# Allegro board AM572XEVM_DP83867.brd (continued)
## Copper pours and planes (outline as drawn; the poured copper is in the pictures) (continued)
GND on TOP: 96.37,66.14 96.37,72.24 99.92,72.24 99.92,66.14
GND on TOP: 28.07,76.96 28.07,81.66 27.81,81.92 23.5,81.92 22.35,83.06 22.35,93.22 22.86,93.73 27.39,93.73 27.79,93.32 27.79,87.18 28.11,86.87 29.72,86.87 30.1,86.49 30.1,83.44 30.61,82.93 30.61,80.52 30.86,80.26 35.69,80.26 35.81,80.14 35.81,78.99 35.69,78.87 34.04,78.87 33.4,79.5 30.86,79.5 30.61,79.25 30.61,76.96 30.86,76.71 32.13,76.71 32.26,76.58 32.26,75.95 32.13,75.82 26.54,75.82 26.42,75.95 26.42,76.58 26.54,76.71 27.81,76.71
GND on TOP: 82.58,65.66 82.58,71.75 86.13,71.75 86.13,65.66
GND on TOP: 109.47,24.13 109.47,36.96 111.38,36.96 111.38,24.13
GND on TOP: 101.6,40.89 101.6,45.59 101.35,45.85 99.44,45.85 98.74,46.55 98.74,52.22 99.45,52.93 100.65,52.93 103.31,50.27 103.31,47.69 104.14,46.86 104.14,44.45 104.39,44.2 108.08,44.2 108.2,44.07 108.2,43.56 108.08,43.43 104.39,43.43 104.14,43.18 104.14,40.89 104.39,40.64 105.66,40.64 105.79,40.51 105.79,39.88 105.66,39.75 100.08,39.75 99.95,39.88 99.95,40.51 100.08,40.64 101.35,40.64
GND on BOTTOM: 55.44,28.77 79.18,28.77 79.18,52.51 55.44,52.51 ; 6 cut-outs
GND on BOTTOM: 28.58,73.15 32.39,73.15 32.64,72.9 32.64,71.37 32.39,71.12 28.58,71.12 28.32,71.37 28.32,72.9
GND on BOTTOM: 46.04,25.39 46.04,24.43 46.29,24.18 47.05,24.18 47.5,24.63 47.5,24.75 47.31,24.94 47.24,24.94 46.74,24.5 46.48,24.5 46.36,24.63 46.36,25.32 46.29,25.39
GND on BOTTOM: 89.59,73.05 88.06,71.53 85.5,71.53 83.39,69.42 83.39,62.48 87.3,58.57 93.01,58.57 96.24,61.8 96.24,63.09 96.39,63.25 97.74,63.25 98.2,63.7 98.2,65.81 97,67.01 97,71.07 95.02,73.05
GND on BOTTOM: 103.5,44.58 103.76,44.32 103.76,41.78 104.01,41.53 105.66,41.53 105.79,41.4 105.79,39.88 105.66,39.75 100.2,39.75 100.08,39.88 100.08,40.64 100.2,40.77 100.58,40.77 100.71,40.89 100.71,42.16 100.58,42.29 100.2,42.29 100.08,42.42 100.08,42.67 100.2,42.8 101.73,42.8 101.98,43.05 101.98,44.32 102.23,44.58
GND on BOTTOM: 60.81,82.09 60.81,82.96 61.06,83.21 63.37,83.21 63.73,82.85 63.73,81.46 63.45,81.18 62.94,81.18 62.23,81.89 61.01,81.89
GND on BOTTOM: 103.76,50.55 103.76,49.15 103.5,48.9 99.7,48.9 99.44,49.15 99.44,50.55 99.7,50.8 103.5,50.8
GND on BOTTOM: 97.51,70.89 97.51,67.74 98.73,66.52 98.73,63.45 99.29,62.89 100.13,62.89 100.94,62.08 100.94,59.54 101.65,58.83 109.25,58.83 109.87,59.45 109.87,62.62 111.68,64.44 111.68,69.19 107.62,73.25 102.06,73.25 102.03,73.28 99.9,73.28
GND on BOTTOM: 25.91,87.12 31.9,87.12 32.44,86.58 32.44,85.15 32.39,85.09 25.91,85.09 25.78,85.22 25.78,87
GND on BOTTOM: 46.04,47.79 46.04,46.84 46.29,46.58 47.05,46.58 47.5,47.03 47.5,47.16 47.31,47.35 47.24,47.35 46.74,46.9 46.48,46.9 46.36,47.03 46.36,47.73 46.29,47.79
GND on BOTTOM: 67.06,62.74 66.8,62.48 65.02,62.48 64.77,62.74 64.77,63.75 65.02,64.01 66.8,64.01 67.06,63.75
GND on BOTTOM: 46.04,58.99 46.04,58.04 46.29,57.78 47.05,57.78 47.5,58.23 47.5,58.36 47.31,58.55 47.24,58.55 46.74,58.1 46.48,58.1 46.36,58.23 46.36,58.93 46.29,58.99
GND on BOTTOM: 71.12,63.5 71.37,63.75 73.15,63.75 73.41,63.5 73.41,61.98 73.15,61.72 72.9,61.72 72.39,62.23 71.37,62.23 71.12,62.48
GND on BOTTOM: 56.77,65.48 56.77,66.65 56.34,67.08 56.34,67.49 56.44,67.59 57.76,67.59 58.39,66.95 58.39,65.81 57.91,65.33 56.92,65.33
GND on BOTTOM: 32.39,66.8 32.64,66.55 32.64,64.64 32.89,64.39 34.54,64.39 34.67,64.26 34.67,64.01 34.54,63.88 32.77,63.88 28.96,63.88 28.83,64.01 28.83,65.28 28.96,65.41 30.61,65.41 30.86,65.66 30.86,66.55 31.12,66.8
GND on BOTTOM: 66.9,83.77 66.37,83.77 65.81,83.21 64.21,83.21 64.06,83.06 64.06,81.94 64.13,81.86 65.91,81.86 66.19,81.58 66.19,81.31 66.42,81.08 66.93,81.08 67.06,81.2 67.06,81.64 67.26,81.84 69.09,81.84 69.27,82.02 69.27,82.91 68.96,83.21 67.46,83.21
GND on BOTTOM: 83.57,79.5 83.57,89.15 83.82,89.41 86.36,89.41 86.61,89.15 86.61,79.5 86.36,79.25 83.82,79.25
GND on BOTTOM: 72.29,83.21 69.7,83.21 69.49,83.01 69.49,81.18 69.72,80.95 70.13,80.95 70.38,81.2 70.38,81.58 70.61,81.81 72.29,81.81 72.59,82.12 72.59,82.91
GND on BOTTOM: 27.18,46.61 27.43,46.86 30.73,46.86 30.73,48.26 30.86,48.39 31.24,48.39 31.5,48.13 31.5,42.8 31.24,42.55 27.43,42.55 27.18,42.8
GND on BOTTOM: 62.23,62.74 61.98,62.48 60.2,62.48 59.94,62.74 59.94,63.75 60.2,64.01 61.98,64.01 62.23,63.75
GND on BOTTOM: 57.4,62.74 57.15,62.48 55.37,62.48 55.12,62.74 55.12,63.75 55.37,64.01 57.15,64.01 57.4,63.75
GND on BOTTOM: 29.97,80.77 30.23,80.52 30.23,77.98 29.97,77.72 29.46,77.72 29.34,77.6 29.34,77.09 29.46,76.96 32.13,76.96 32.26,76.83 32.26,76.07 32.13,75.95 26.54,75.95 26.42,76.07 26.42,78.87 26.54,78.99 28.19,78.99 28.45,79.25 28.45,80.52 28.7,80.77
GND on GND_L2, GND_L4, GND_L11: outline of 82 points within 14.1,1.52 123.06,106.05
GND on PWR_L6: 86.49,7.87 86.74,7.62 107.82,7.62 112.78,12.57 112.78,39.62 112.52,39.88 111.38,39.88 111,40.26 111,42.16 110.74,42.42 104.65,42.42 104.39,42.16 104.39,34.16 104.01,33.78 99.31,33.78 99.06,33.53 99.06,24.13 98.68,23.75 86.74,23.75 86.49,23.5
GND on GND_L9: outline of 82 points within 14.1,1.52 123.06,106.05 ; 14 cut-outs
GND_EARTH on BOTTOM (solid shape): 88.03,0.2 84.69,0.2 84.69,2.7 88.03,2.7
GND_EARTH on BOTTOM (solid shape): 84.5,4.03 84.28,4.03 84.28,1 84.16,0.72 83.88,0.6 83.38,0.6 83.09,0.72 82.97,1 82.97,3.05 82.5,3.05 82.5,5.43 84.5,5.43
GND_EARTH on BOTTOM (solid shape): 90.22,3.05 89.72,3.05 89.72,1 89.61,0.72 89.33,0.6 88.82,0.6 88.54,0.72 88.42,1 88.42,4.03 88.22,4.03 88.22,5.43 90.22,5.43
GND_EARTH on TOP, BOTTOM, GND_L2, INT_L3, GND_L4, SIG_L5, PWR_L6, PWR_L7, SIG_L8, GND_L9, SIG_L10, GND_L11: outline of 95 points within 13.08,0.38 124.08,107.19
GND_SIGNAL on SIG_L8: 24.89,1.52 24.64,1.78 24.64,14.73 24.89,14.99 45.97,14.99 51.69,20.7 51.69,23.62 51.94,23.88 62.48,23.88 62.87,23.5 62.87,12.45 62.61,12.19 52.32,12.19 51.44,11.3 51.44,1.78 51.18,1.52
VDD_1.1 on PWR_L6: 86.49,36.96 86.74,37.21 97.28,37.21 97.66,37.59 97.66,42.16 97.92,42.42 103.89,42.42 104.14,42.16 104.14,34.29 103.89,34.04 99.19,34.04 98.81,33.66 98.81,24.26 98.55,24 86.74,24 86.49,24.26
VDD_1V0 on TOP: 55.63,66.9 55.19,67.34 54.08,67.34 53.8,67.06 53.8,65.46 54.33,64.92 55.45,64.92 55.63,65.1
VDD_1V0 on TOP: 86.69,74.27 86.69,75.59 87.02,75.92 87.6,75.92 87.91,75.62 87.91,74.63 87.5,74.22 86.74,74.22
VDD_1V0 on TOP: 111.25,74.93 111.25,75.31 110.97,75.59 110.97,76.15 111.4,76.58 111.89,76.58 112.34,76.12 112.34,75.59 112.06,75.31 112.06,74.88 111.3,74.88
VDD_1V0 on BOTTOM: 56.11,66.55 55.65,67.01 54.33,67.01 54.13,66.8 54.13,65.23 54.41,64.95 55.75,64.95 56.11,65.3
VDD_1V0 on SIG_L8: 54.76,67.26 53.77,67.26 51.26,69.77 45.75,69.77 44.96,70.56 42.32,70.56 41.38,71.5 41.38,76.78 44.88,80.29 44.88,85.93 45.87,86.92 75.62,86.92 75.95,86.59 79.4,86.59 85.67,80.31 85.67,75.74 86.44,74.98 112.65,74.98 112.93,75.26 112.93,76.86 112.52,77.27 89.61,77.27 88.9,77.98 88.9,81.76 80.44,90.22 49.68,90.22 48.69,91.21 44.32,91.21 37.36,84.25 37.36,71.12 40.84,67.64 44.98,67.64 45.57,67.06 51.1,67.06 52.2,65.96 53.44,65.96 54.05,65.35 54.81,65.35 55.07,65.61 55.07,66.95
VDD_1V8 on TOP: 56.64,59.44 56.64,60.45 56.9,60.71 58.67,60.71 58.93,60.45 58.93,59.44 58.67,59.18 56.9,59.18
VDD_1V8 on BOTTOM: 58.93,59.44 58.67,59.18 56.9,59.18 56.64,59.44 56.64,60.45 56.9,60.71 58.67,60.71 58.93,60.45
VDD_1V8 on PWR_L7: 57.28,54.74 57.28,66.29 54.74,68.83 54.74,70.1 54.99,70.36 66.29,70.36 66.55,70.1 66.55,48.64 65.91,48.01 65.91,44.7 65.66,44.45 63.37,44.45 63.12,44.7 63.12,58.04 64.01,58.93 64.01,60.83 63.63,61.21 59.94,61.21 59.56,60.83 59.56,54.74 59.31,54.48 57.53,54.48
VDD_1V8 on PWR_L7: 72.64,42.16 72.77,42.04 74.8,42.04 74.93,42.16 74.93,46.61 74.8,46.74 73.53,46.74 73.41,46.61 73.41,44.2 73.15,43.94 72.9,43.94 72.64,43.69
VDD_1V8 on SIG_L8: 63.25,69.09 63.25,68.33 62.99,68.07 62.61,68.07 61.59,69.09 61.59,72.14 61.85,72.39 69.98,72.39 69.98,72.39 73.66,72.39 75.44,74.17 78.99,74.17 79.25,73.91 79.25,69.98 78.99,69.72 63.88,69.72
VDD_1V8 on SIG_L10: 60.45,34.42 60.45,46.35 60.71,46.61 64.26,46.61 64.39,46.48 64.39,45.34 64.64,45.09 65.15,45.09 66.04,44.2 68.2,44.2 68.45,43.94 68.45,43.31 68.83,42.93 73.28,42.93 73.53,42.67 73.53,34.42 73.28,34.16 60.71,34.16
VDD_2V5 on TOP: 109.17,74.93 109.17,75.31 108.89,75.59 108.89,76.15 109.32,76.58 109.8,76.58 110.26,76.12 110.26,75.59 109.98,75.31 109.98,74.88 109.22,74.88
VDD_2V5 on TOP: 85.26,74.19 84.89,74.19 84.68,73.98 84.26,73.98 84.02,74.22 84.02,75.25 84.13,75.35 84.67,75.35 84.94,75.08 85.38,75.08 85.38,74.31
VDD_2V5 on TOP: 72.67,84.02 70.46,84.02 70.28,84.2 70.28,85.5 70.66,85.88 72.31,85.88 72.77,85.42 72.77,84.12
VDD_2V5 on BOTTOM: 72.59,84.04 72.34,83.78 70.56,83.78 70.31,84.04 70.31,85.53 70.56,85.79 72.29,85.79 72.59,85.48
VDD_2V5 on PWR_L6: 72.49,85.83 70.51,85.83 70.13,85.45 70.13,83.62 72.24,81.51 83.85,81.51 85.39,79.96 85.39,77.19 84.07,75.87 84.07,74.14 84.28,73.94 85.9,73.94 86.97,75.01 110.16,75.01 110.64,75.49 110.64,76.66 110.06,77.24 91.08,77.24 88.67,79.65 88.67,83.64 87.12,85.19 73.1,85.19
VDD_3V3 on TOP: 43.31,68.2 43.31,67.69 43.56,67.44 43.56,65.79 43.69,65.66 44.83,65.66 44.96,65.79 44.96,68.07 44.7,68.33 43.43,68.33
VDD_3V3 on TOP: 97.64,60.88 96.88,60.88 96.62,60.63 96.62,59.41 96.8,59.23 97.79,59.23 98.22,59.66 98.22,60.3
VDD_3V3 on TOP: 110.62,59.77 110.62,59.18 110.41,58.98 110.41,58.19 110.67,57.94 111.35,57.94 111.63,58.22 111.63,58.98 111.43,59.18 111.43,59.66 111.33,59.77
VDD_3V3 on PWR_L7: outline of 82 points within 14.1,1.52 123.06,106.05 ; 1 cut-out
VDD_3V3 on SIG_L10: 70.1,70.1 69.85,69.85 68.33,69.85 68.07,70.1 68.07,72.39 68.33,72.64 76.58,72.64 76.84,72.39 76.84,71.5 76.58,71.25 76.2,71.25 75.82,70.87 70.48,70.87 70.1,70.48
VDD_3V3_SP on BOTTOM: 80.26,61.21 80.14,61.09 80.14,58.8 80.01,58.67 76.45,58.67 76.2,58.93 76.2,61.98 76.45,62.23 76.45,66.8 76.2,67.06 75.69,67.06 75.69,67.56 76.2,67.56 76.58,67.94 78.49,67.94 79.5,68.96 80.26,68.96 80.65,69.34 80.65,70.1 82.45,70.1 82.91,69.65 82.91,67.87 81.71,66.67 81.71,61.77 81.15,61.21
VDD_CORE on PWR_L6: 72.77,43.18 72.9,43.05 79.5,43.05 79.76,43.31 79.76,44.45 79.5,44.7 73.03,44.7 72.77,44.45
VDD_CORE on SIG_L8: 67.18,44.32 67.94,43.56 69.47,43.56 70.36,44.45 70.36,48.39 70.61,48.64 78.87,48.64 81.79,51.56 81.79,57.53 81.53,57.78 79.63,57.78 79.5,57.91 79.5,74.04 79.12,74.42 75.31,74.42 73.53,72.64 59.44,72.64 57.53,74.55 56.13,74.55 55.88,74.8 55.88,77.09 56.13,77.34 59.56,77.34 60.96,75.95 72.14,75.95 73.15,76.96 84.73,76.96 85.42,76.28 85.42,49.61 80.52,44.7 80.52,43.43 80.39,43.31 79.38,43.31 79.25,43.43 79.25,43.81 78.87,44.2 77.85,44.2 73.15,39.5 73.15,38.86 73.66,38.86 73.91,38.61 73.91,37.85 74.42,37.34 74.42,33.78 74.17,33.53 62.87,33.53 62.61,33.78 62.61,44.07 62.87,44.32
VDD_DDR on TOP: 61.47,59.44 61.47,60.45 61.72,60.71 63.5,60.71 63.75,60.45 63.75,59.44 63.5,59.18 61.72,59.18
VDD_DDR on BOTTOM: 38.99,30.99 39.12,30.86 39.12,30.1 38.86,29.84 37.47,29.84 37.34,29.97 37.34,30.86 37.47,30.99
VDD_DDR on BOTTOM: 63.75,59.44 63.5,59.18 61.72,59.18 61.47,59.44 61.47,60.45 61.72,60.71 63.5,60.71 63.75,60.45
VDD_DDR on INT_L3: 61.47,47.75 61.21,47.5 61.21,46.1 61.47,45.85 63.5,45.85 63.63,45.72 63.63,44.58 63.88,44.32 66.04,44.32 66.29,44.58 66.29,46.74 66.04,46.99 65.66,46.99 64.9,47.75
VDD_DDR on PWR_L6: 53.34,22.99 53.72,23.37 55.24,23.37 55.5,23.62 55.5,34.92 55.88,35.31 62.61,35.31 62.87,35.56 62.87,43.43 64.52,45.09 64.52,48.13 61.21,51.44 55.88,51.44 55.5,51.82 55.5,61.47 54.74,62.23 36.32,62.23 32.51,58.42 32.51,16.26 32.77,16 53.09,16 53.34,16.26
VDD_DDR on PWR_L7: 32.77,16.76 46.99,16.76 52.32,22.1 52.32,24.64 62.87,35.18 62.87,58.17 63.75,59.05 63.75,60.71 63.5,60.96 60.07,60.96 59.82,60.71 59.82,54.61 59.44,54.23 55.75,54.23 55.37,54.61 55.37,57.15 50.29,62.23 36.32,62.23 32.51,58.42 32.51,17.02
VDD_DSP on PWR_L6: 68.71,44.83 68.96,45.09 71.75,45.09 72.01,44.83 72.01,42.8 72.52,42.29 80.39,42.29 80.65,42.55 80.65,44.58 80.01,45.21 80.01,59.05 79.63,59.44 78.23,59.44 77.98,59.69 77.98,80.92 78.33,81.28 83.72,81.28 85.09,79.91 85.09,77.06 83.95,75.92 83.95,71.04 85.09,69.9 85.09,61.09 86.23,59.94 86.23,24.26 85.98,24 68.96,24 68.71,24.26
VDD_DSP on SIG_L8: 56.13,80.01 84.84,80.01 85.09,79.76 85.09,77.47 84.84,77.22 73.03,77.22 72.01,76.2 61.09,76.2 59.69,77.6 56.13,77.6 55.88,77.85 55.88,79.76
VDD_DSP on GND_L9: 71.63,45.34 71.88,45.09 71.88,42.93 71.63,42.67 63.12,42.67 62.87,42.93 62.87,45.09 63.12,45.34
VDD_MPU on PWR_L6: 63.12,12.83 63.12,22.99 62.74,23.37 56.01,23.37 55.75,23.62 55.75,34.8 56.01,35.05 62.74,35.05 63.12,35.43 63.12,43.31 64.77,44.96 64.77,48.26 61.34,51.69 56.01,51.69 55.75,51.94 55.75,61.59 54.86,62.48 54.86,71.88 55.12,72.14 58.17,72.14 58.42,71.88 58.42,66.67 58.8,66.29 69.47,66.29 69.85,66.67 69.85,67.44 69.98,67.56 71.25,67.56 71.37,67.44 71.37,67.06 71.63,66.8 74.17,66.8 74.42,66.55 74.42,65.66 74.8,65.28 77.47,65.28 77.72,65.02 77.72,59.69 77.47,59.44 68.83,59.44 68.45,59.05 68.45,24.26 68.2,24 67.44,24 67.06,23.62 67.06,11.68 66.65,11.28 63.3,11.28 62.76,10.74 62.76,9.47 63.07,9.17 63.32,9.17 63.7,8.79 63.7,7.98 63.35,7.62 60.96,7.62 60.71,7.87 60.71,12.19 60.96,12.45 62.74,12.45
VDD_MPU on SIG_L8: 61.34,68.96 62.48,67.82 71.37,67.82 72.01,67.18 74.3,67.18 74.42,67.06 74.42,65.41 74.17,65.15 61.09,65.15 58.52,67.72 58.52,69.37 58.04,69.85 54.99,69.85 54.36,70.48 54.36,71.88 54.61,72.14 61.09,72.14 61.34,71.88
VDD_RTC on PWR_L7: 74.3,74.3 74.17,74.17 69.85,74.17 69.47,73.79 69.47,55.63 69.09,55.24 69.09,48.39 68.07,47.37 68.07,44.7 67.82,44.45 66.42,44.45 66.17,44.7 66.17,47.88 66.8,48.51 66.8,75.95 66.93,76.07 74.04,76.07 74.3,75.82
VDD_SD on INT_L3: 72.77,44.07 73.15,44.45 73.15,45.59 73.03,45.72 71.88,45.72 71.63,45.47 71.63,41.4 70.87,40.64 70.87,29.59 69.47,28.19 69.47,20.5 69.29,20.32 69.29,15.16 69.62,14.83 71.02,14.83 71.37,15.19 71.37,16.48 71.63,16.74 71.63,24.77 72.26,25.4 72.26,28.07 72.77,28.57
VDD_SD on PWR_L6: 64.52,7.62 64.26,7.87 64.26,9.37 64.03,9.6 63.7,9.6 63.53,9.42 63.12,9.42 62.94,9.6 62.94,10.69 63.37,11.13 66.9,11.13 67.31,11.53 67.31,23.5 67.56,23.75 85.98,23.75 86.23,23.5 86.23,7.87 85.98,7.62
VDD_SD on PWR_L7: 74.04,52.45 74.04,65.79 73.79,66.04 73.79,68.45 74.04,68.71 74.04,73.66 73.79,73.91 69.98,73.91 69.72,73.66 69.72,72.77 69.98,72.52 70.36,72.52 70.48,72.64 70.48,73.03 70.74,73.28 71.25,73.28 72.64,71.88 72.64,54.86 71.5,53.72 71.5,44.45 71.75,44.2 73.03,44.2 73.15,44.32 73.15,46.86 73.28,46.99 73.28,51.69
VDD_SHV5 on PWR_L7: 68.33,41.4 68.58,41.15 70.36,41.15 70.61,41.4 70.61,43.81 71.25,44.45 71.25,53.85 72.39,54.99 72.39,71.75 71.12,73.03 70.87,73.03 70.74,72.9 70.74,72.52 70.48,72.26 69.98,72.26 69.72,72.01 69.72,55.5 69.34,55.12 69.34,48.26 68.33,47.24
VDDA_1V8_PHYA on BOTTOM: 62.99,66.29 61.85,66.29 61.59,66.55 61.59,69.09 61.85,69.34 63.75,69.34 64.01,69.09 64.01,68.71 63.75,68.45 63.37,68.45 62.87,67.94 62.87,66.93 63.12,66.67 63.12,66.42
VDDA_1V8_PHYA on BOTTOM: 76.96,57.02 77.09,57.15 77.09,58.29 76.96,58.42 76.2,58.42 76.07,58.29 76.07,57.15 76.2,57.02
VDDA_1V8_PHYA on PWR_L6: 69.34,45.47 69.34,46.61 69.98,47.24 78.61,47.24 79.12,47.75 79.5,47.75 79.76,48.01 79.76,58.93 79.5,59.18 68.96,59.18 68.71,58.93 68.71,45.59 68.83,45.47
VDDA_1V8_PHYA on SIG_L8: 71.5,68.07 63.75,68.07 63.5,68.33 63.5,68.96 64.01,69.47 78.99,69.47 79.25,69.22 79.25,57.91 79.12,57.78 76.2,57.78 75.95,58.04 75.95,65.91 74.42,67.44 72.14,67.44
VDDA_1V8_PHYB on BOTTOM: 74.8,57.02 74.93,57.15 74.93,58.29 74.8,58.42 74.04,58.42 73.91,58.29 73.91,57.15 74.04,57.02
VDDA_1V8_PHYB on BOTTOM: 64.13,66.29 64.26,66.42 64.26,67.94 64.01,68.2 63.5,68.2 63.25,67.94 63.25,66.93 63.5,66.67 63.5,66.42 63.63,66.29
VDDA_1V8_PHYB on GND_L9: 74.93,58.04 74.8,57.91 73.79,57.91 73.03,58.67 67.06,58.67 66.8,58.93 66.8,65.02 66.55,65.28 63.5,65.28 63.25,65.53 63.25,68.2 63.5,68.45 64.13,68.45 64.39,68.2 64.39,66.55 64.64,66.29 67.82,66.29 67.94,66.17 67.94,59.82 68.2,59.56 73.91,59.56 74.93,58.55
VDDA_1V8_PLL on BOTTOM: 65.66,48.77 65.79,48.64 66.17,48.64 66.42,48.9 66.42,54.86 65.66,55.63 62.23,55.63 62.1,55.5 62.1,54.86 62.23,54.74 63.12,54.74 63.37,54.48 65.91,54.48 65.91,53.47 65.79,53.34 65.53,53.34 65.15,52.96 65.15,49.53 65.66,49.02
VSSA_OSC0 on TOP: 65.53,57.66 65.79,57.4 65.79,54.23 57.28,54.23 57.02,54.48 57.02,57.4 57.28,57.66
VSSA_OSC1 on TOP: 71.63,57.66 71.88,57.4 71.88,55.24 70.87,54.23 66.29,54.23 66.04,54.48 66.04,57.4 66.29,57.66
(no net) on TOP: outline of 82 points within 14.1,1.52 123.06,106.05 ; 75 cut-outs
DDR_REFIN on TOP: 29.97,17.65 29.97,19.94 30.1,20.07 30.61,20.07 30.73,19.94 30.73,18.92 30.86,18.8 31.24,18.8 31.37,18.67 31.37,18.41 31.24,18.29 30.48,18.29 30.35,18.16 30.35,17.65 30.23,17.53 30.1,17.53
DDR_VREFSTL1 on BOTTOM: 38.61,53.39 39.12,53.9 39.12,54.99 38.99,55.12 38.1,55.12 37.85,54.86 37.9,54.86 38.1,54.66 38.1,53.52 38.23,53.39
DDR_VREFSTL1 on SIG_L5: 38.1,42.34 38.35,42.09 38.86,42.09 39.12,42.34 39.12,43.94 38.99,44.07 37.97,44.07 37.85,43.94 37.85,43.81 38.1,43.56
DDR_VREFSTL1 on SIG_L5: 58.8,45.09 64.26,45.09 64.52,45.34 64.52,45.85 64.26,46.1 58.8,46.1 58.42,45.72 58.42,45.47
DDR_VREFSTL2 on BOTTOM: 60.45,39.37 60.45,40.13 60.33,40.26 60.33,40.89 60.45,41.02 60.58,41.02 60.71,40.89 60.71,40.64 60.83,40.51 61.21,40.51 61.47,40.26 61.47,39.37 61.09,38.99 60.83,38.99
DDR_VREFSTL2 on BOTTOM: 38.73,31.11 39.12,31.5 39.12,32.51 38.99,32.64 37.97,32.64 37.85,32.51 38.1,32.26 38.1,31.24 38.23,31.11
DDR_VREFSTL2 on SIG_L5: 38.1,19.94 38.35,19.68 38.86,19.68 39.12,19.94 39.12,21.46 38.99,21.59 37.85,21.59 37.85,21.46 38.1,21.21
EEWP on BOTTOM (solid shape): 43.94,76.24 43.96,76.2 43.94,76.16 43.26,75.48 42.53,76.2 43.26,76.92
ETH0_1V0 on TOP: 86.69,73.34 86.69,72.9 86.46,72.67 86.46,72.11 86.73,71.84 87.57,71.84 87.78,72.06 87.78,72.59 87.5,72.87 87.5,73.24 87.4,73.34
ETH0_1V0 on PWR_L7: 86.21,63.5 86.21,65.15 87.27,66.22 87.27,69.34 86.21,70.41 86.21,72.52 86.46,72.77 95.86,72.77 96.11,72.52 96.11,67.08 96.85,66.34 96.85,65.3 96.11,64.57 96.11,62.41 93.93,60.22 88.98,60.22 86.44,62.76 86.46,62.79 86.46,63.25
ETH0_2V5 on TOP: 85.27,72.65 84.95,72.65 84.74,72.44 84.27,72.44 84.03,72.68 84.03,73.54 84.23,73.74 84.68,73.74 84.89,73.53 85.39,73.53 85.39,72.77
ETH0_2V5 on PWR_L6: 84.25,73.71 86.13,73.71 87.15,74.73 94.28,74.73 94.67,74.35 94.67,71.78 93.85,70.97 93.32,70.97 93.19,70.84 92.81,70.84 92.68,70.97 90.32,70.97 90.14,70.79 89.87,70.79 89.69,70.97 88.77,70.97 88.49,70.69 84.48,70.69 84.1,71.07 84.1,73.56
ETH0_3V3 on TOP: 97.74,61.54 97.08,61.54 96.65,61.98 96.65,62.99 96.85,63.2 97.69,63.2 98.22,62.66 98.22,62.03
ETH0_3V3 on PWR_L6: 85.22,70.26 85.22,61.29 86.56,59.94 97.71,59.94 98.02,60.25 98.02,63.8 97.31,64.52 97.31,74.55 97.16,74.7 95.15,74.7 94.92,74.47 94.92,70.87 94.51,70.46 85.42,70.46
ETH1_1V0 on TOP: 111.25,73.51 111.25,72.92 111,72.67 111,72.21 111.25,71.96 112.12,71.96 112.39,72.24 112.39,72.59 112.06,72.92 112.06,73.41 111.96,73.51
ETH1_1V0 on PWR_L7: 102.97,73.05 112.37,73.05 112.62,72.8 112.62,70.76 110.59,68.73 110.59,64.24 109.89,63.54 109.89,62.93 107.52,60.55 103.4,60.55 101.73,62.23 100.71,62.23 99.8,63.14 99.8,65.53 100.91,66.65 100.91,70.99
ETH1_2V5 on TOP: 109.17,73.51 109.17,72.92 108.89,72.64 108.89,72.26 109.14,72.01 109.98,72.01 110.26,72.29 110.26,72.64 109.98,72.92 109.98,73.41 109.88,73.51
ETH1_2V5 on PWR_L6: 102.97,74.73 102.44,74.19 102.44,71.91 103.3,71.04 103.96,71.04 104.14,71.22 104.85,71.22 105.21,70.87 105.36,70.87 105.77,71.27 106.25,71.27 106.58,70.94 106.88,70.94 107.19,71.25 111.33,71.25 111.56,71.48 111.56,74.35 111.18,74.73
ETH1_3V3 on TOP: 110.62,61.19 110.62,61.57 110.34,61.85 110.34,62.41 110.77,62.84 111.25,62.84 111.71,62.38 111.71,61.85 111.43,61.57 111.43,61.14 110.67,61.14
ETH1_3V3 on PWR_L6: 98.45,59.99 111.1,59.99 111.51,60.4 111.51,70.51 111.12,70.89 102.82,70.89 102.18,71.53 102.18,74.3 101.78,74.7 98.58,74.7 97.76,73.89 97.76,64.67 98.22,64.21 98.22,60.22
LDO_VRTC on BOTTOM (solid shape): 75.34,60.34 74.84,59.85 74.08,59.85 73.99,59.94 74.77,60.72
LDO_VRTC on SIG_L10: 67.44,47.37 67.44,54.61 73.53,60.71 75.31,60.71 75.56,60.45 75.56,60.2 75.31,59.94 73.91,59.94 68.83,54.86 68.83,47.37 68.45,46.99 67.82,46.99
MMC2_3V3 on PWR_L6: 97.16,37.47 86.74,37.47 86.49,37.72 86.49,59.56 86.74,59.82 97.16,59.82 97.41,59.56 97.41,37.72
Net_213 on PWR_L6: 10.67,0.38 10.67,6.99 11.18,7.49 12.32,7.49 12.32,94.11 11.18,94.11 10.67,94.61 10.67,106.93 0.38,106.93 0.38,0.38
Net_214 on GND_L11: 10.67,0.38 10.67,6.99 11.18,7.49 12.32,7.49 12.32,94.11 11.18,94.11 10.67,94.61 10.67,107.14 0.38,107.14 0.38,0.38
Net_215 on GND_L11: 126.49,0.38 126.49,6.99 125.98,7.49 124.84,7.49 124.84,94.11 125.98,94.11 126.49,94.61 126.49,106.93 136.78,106.93 136.78,0.38
Net_216 on SIG_L10: 10.67,0.38 10.67,6.99 11.18,7.49 12.32,7.49 12.32,94.11 11.18,94.11 10.67,94.61 10.67,106.86 0.38,106.86 0.38,0.38
Net_217 on SIG_L10: 126.49,0.38 126.49,6.99 125.98,7.49 124.84,7.49 124.84,94.11 125.98,94.11 126.49,94.61 126.49,106.93 136.78,106.93 136.78,0.38
Net_218 on GND_L9: 10.67,0.38 10.67,6.99 11.18,7.49 12.32,7.49 12.32,94.11 11.18,94.11 10.67,94.61 10.67,107.19 0.38,107.19 0.38,0.38
Net_219 on GND_L9: 126.49,0.38 126.49,6.99 125.98,7.49 124.84,7.49 124.84,94.11 125.98,94.11 126.49,94.61 126.49,107.14 136.78,107.14 136.78,0.38
Net_220 on SIG_L8: 10.67,0.38 10.67,6.99 11.18,7.49 12.32,7.49 12.32,94.11 11.18,94.11 10.67,94.61 10.67,107.09 0.38,107.09 0.38,0.38
Net_221 on SIG_L8: 126.49,0.38 126.49,6.99 125.98,7.49 124.84,7.49 124.84,94.11 125.98,94.11 126.49,94.61 126.49,106.98 136.78,106.98 136.78,0.38
Net_222 on PWR_L7: 10.67,0.38 10.67,6.99 11.18,7.49 12.32,7.49 12.32,94.11 11.18,94.11 10.67,94.61 10.67,107.09 0.38,107.09 0.38,0.38
Net_223 on PWR_L7: 126.49,0.38 126.49,6.99 125.98,7.49 124.84,7.49 124.84,94.11 125.98,94.11 126.49,94.61 126.49,107.09 136.78,107.09 136.78,0.38
Net_224 on PWR_L6: 126.49,0.38 126.49,6.99 125.98,7.49 124.84,7.49 124.84,94.11 125.98,94.11 126.49,94.61 126.49,106.98 136.78,106.98 136.78,0.38
Net_225 on SIG_L5: 10.67,0.38 10.67,6.99 11.18,7.49 12.32,7.49 12.32,94.11 11.18,94.11 10.67,94.61 10.67,106.93 0.38,106.93 0.38,0.38
Net_226 on SIG_L5: 126.49,0.38 126.49,6.99 125.98,7.49 124.84,7.49 124.84,94.11 125.98,94.11 126.49,94.61 126.49,106.88 136.78,106.88 136.78,0.38
Net_227 on GND_L4: 10.67,0.38 10.67,6.99 11.18,7.49 12.32,7.49 12.32,94.11 11.18,94.11 10.67,94.61 10.67,106.73 0.38,106.73 0.38,0.38
Net_228 on GND_L4: 126.49,0.38 126.49,6.99 125.98,7.49 124.84,7.49 124.84,94.11 125.98,94.11 126.49,94.61 126.49,106.93 136.78,106.93 136.78,0.38
Net_229 on INT_L3: 126.49,0.38 126.49,6.99 125.98,7.49 124.84,7.49 124.84,94.11 125.98,94.11 126.49,94.61 126.49,106.88 136.78,106.88 136.78,0.38
Net_230 on INT_L3: 10.67,0.38 10.67,6.99 11.18,7.49 12.32,7.49 12.32,94.11 11.18,94.11 10.67,94.61 10.67,106.98 0.38,106.98 0.38,0.38
Net_231 on GND_L2: 10.67,0.38 10.67,6.99 11.18,7.49 12.32,7.49 12.32,94.11 11.18,94.11 10.67,94.61 10.67,107.01 0.38,107.01 0.38,0.38
Net_231 on GND_L2: 126.49,0.38 126.49,6.99 125.98,7.49 124.84,7.49 124.84,94.11 125.98,94.11 126.49,94.61 126.49,106.76 136.78,106.76 136.78,0.38
PS_3V3 on TOP: 43.43,70.1 43.31,70.23 43.31,70.74 43.56,70.99 43.56,71.25 43.81,71.5 44.7,71.5 44.96,71.25 44.96,70.36 44.7,70.1
PS_3V3 on PWR_L6: 32.26,58.55 36.2,62.48 54.36,62.48 54.61,62.74 54.61,72.01 54.99,72.39 58.29,72.39 58.67,72.01 58.67,66.8 58.93,66.55 69.34,66.55 69.6,66.8 69.6,67.56 69.85,67.82 71.37,67.82 71.63,67.56 71.63,67.18 71.75,67.06 74.42,67.06 74.68,66.8 74.68,65.79 74.93,65.53 77.47,65.53 77.72,65.79 77.72,81.03 77.37,81.38 72.09,81.38 69.98,83.49 69.98,84.66 69.55,85.09 49.02,85.09 48.77,84.84 48.77,82.68 48.39,82.3 45.21,82.3 44.96,82.04 44.96,77.34 44.58,76.96 28.19,76.96 27.94,76.71 27.94,16.26 28.19,16 32,16 32.26,16.26
PS_3V3_TAP on TOP: 36.07,86.36 32.77,86.36 32,87.12 30.23,87.12 29.97,87.38 29.97,93.73 30.23,93.98 38.86,93.98 39.37,93.47 39.37,88.65 39.88,88.14 45.34,88.14 51.31,82.17 51.31,80.52 51.05,80.26 37.08,80.26 36.83,80.52 36.83,85.6
SMPS6 on TOP: 59.94,84.33 59.94,85.34 60.2,85.6 61.98,85.6 62.23,85.34 62.23,84.33 61.98,84.07 60.2,84.07
SMPS6 on BOTTOM: 59.94,84.33 59.94,85.34 60.2,85.6 61.98,85.6 62.23,85.34 62.23,83.97 62.08,83.82 60.45,83.82
SMPS6 on SIG_L5: 61.09,86.11 60.83,86.36 45.72,86.36 45.47,86.11 45.47,75.18 45.72,74.93 58.42,74.93 58.67,75.18 58.67,80.67 60.81,82.8 60.83,82.8 61.09,83.06
SMPS_1_2 on TOP: 66.29,59.44 66.29,60.45 67.31,61.47 68.33,61.47 68.58,61.21 68.58,59.44 68.33,59.18 66.55,59.18
SMPS_1_2 on TOP: 69.6,59.44 69.6,61.21 69.85,61.47 70.87,61.47 71.88,60.45 71.88,59.44 71.63,59.18 69.85,59.18
SMPS_1_2 on BOTTOM: 69.6,59.69 69.6,61.21 69.85,61.47 70.1,61.47 70.61,60.96 71.63,60.96 71.88,60.71 71.88,59.69 71.63,59.44 69.85,59.44
SMPS_1_2 on BOTTOM: 66.29,59.69 66.29,60.71 66.55,60.96 67.56,60.96 68.07,61.47 68.33,61.47 68.58,61.21 68.58,59.69 68.33,59.44 66.55,59.44
SMPS_1_2 on SIG_L8: 60.96,64.9 58.29,67.56 58.29,69.22 57.85,69.66 54.8,69.66 54.09,70.37 54.09,71.79 53.49,72.39 45.97,72.39 45.72,72.14 45.72,70.36 45.97,70.1 52.2,70.1 52.7,69.6 52.7,68.58 53.9,67.39 54.91,67.39 55.58,66.73 55.58,65.07 58.8,61.85 64.01,61.85 66.17,59.69 70.36,59.69 70.61,59.94 70.61,61.59 67.31,64.9
SMPS_4/5 on TOP: 63.78,84.15 63.78,85.6 64.01,85.83 65.76,85.83 66.09,85.5 66.09,84.15 66.01,84.07 63.86,84.07
SMPS_4/5 on TOP: 67.21,84.12 67.21,85.57 67.44,85.8 69.19,85.8 69.49,85.5 69.49,84.23 69.32,84.05 67.28,84.05
SMPS_4/5 on BOTTOM: 69.47,84.05 69.22,83.79 67.44,83.79 67.18,84.05 67.18,85.55 67.44,85.8 69.16,85.8 69.47,85.5
SMPS_4/5 on BOTTOM: 66.04,83.97 65.86,83.79 64.08,83.79 63.83,84.05 63.83,85.55 64.11,85.83 65.71,85.83 66.04,85.5
SMPS_4/5 on SIG_L8: 70.61,86.11 70.36,86.36 45.72,86.36 45.47,86.11 45.47,77.85 45.72,77.6 55.37,77.6 55.63,77.85 55.63,79.88 56.01,80.26 70.36,80.26 70.61,80.52
SW1 on TOP: 72.39,62.48 72.64,62.74 72.64,65.02 70.87,66.8 69.22,66.8 68.71,67.31 68.71,68.83 68.2,69.34 68.07,69.22 68.07,66.17 69.22,65.02 69.22,62.74 69.47,62.48
SW1 on SIG_L5: 69.09,62.48 69.09,65.41 68.33,66.17 68.33,69.09 68.58,69.34 71.12,69.34 71.37,69.09 71.37,62.48 71.12,62.23 69.34,62.23
SW2 on TOP: 65.53,62.74 65.79,62.48 68.71,62.48 68.96,62.74 68.96,64.9 67.82,66.04 67.82,68.96 67.44,69.34 67.31,69.34 66.93,68.96 66.93,67.31 65.53,65.91
SW2 on SIG_L5: 66.55,62.23 68.58,62.23 68.83,62.48 68.83,65.28 68.07,66.04 68.07,69.09 67.82,69.34 66.55,69.34 66.29,69.09 66.29,62.48
SW3 on TOP: 65.15,69.22 65.02,69.34 64.77,69.34 64.39,68.96 64.39,67.18 64.01,66.8 62.87,66.8 60.71,64.64 60.71,62.74 60.96,62.48 64.39,62.48 64.64,62.74 64.64,64.9 65.28,65.53 65.28,66.8 65.15,66.93
SW3 on SIG_L5: 62.99,62.48 62.99,69.09 63.25,69.34 65.79,69.34 66.04,69.09 66.04,62.48 65.79,62.23 63.25,62.23
SW4 on TOP: 66.68,75.44 66.42,75.44 66.29,75.56 66.29,78.36 66.98,79.04 66.98,82.68 67.28,82.98 69.39,82.98 69.55,82.83 69.55,80.01 67.44,77.98 67.18,77.72 67.18,75.95
SW4 on SIG_L5: 68.76,82.55 69.44,81.86 69.44,79.1 68.3,77.95 68.3,75.69 68.05,75.44 66.55,75.44 66.29,75.69 66.29,82.3 66.55,82.55
SW5 on TOP: 65.91,75.44 65.66,75.44 65.15,75.95 65.15,77.98 64.77,78.36 64.77,79.91 63.83,80.85 63.83,83.01 66.07,83.01 66.24,82.83 66.24,81.36 66.85,80.75 66.85,79.3 66.04,78.49 66.04,75.56
SW5 on SIG_L5: 65.79,82.55 66.04,82.3 66.04,75.69 65.79,75.44 63.37,75.44 63.12,75.69 63.12,82.3 63.37,82.55
SW6 on TOP: 62.74,74.04 62.74,73.91 62.61,73.79 60.2,73.79 59.44,74.55 59.44,81.97 60.48,83.01 62.59,83.01 62.71,82.88 62.71,78.46 62.23,77.98 61.34,77.98 61.09,77.72 61.09,75.18 61.72,74.55 62.23,74.55
SW6 on SIG_L5: 59.82,73.66 58.93,74.55 58.93,80.47 60.45,81.99 62.53,81.99 62.87,81.66 62.87,73.91 62.61,73.66
SW7 on TOP: 68.83,75.39 69.24,75.39 69.57,75.72 69.57,77.9 70.71,79.04 72.57,79.04 72.95,79.43 72.95,82.78 72.69,83.03 70.54,83.03 70.31,82.8 70.31,80.59 68.78,79.07 68.78,75.44
SW7 on SIG_L5: 70.33,75.56 69.39,75.56 68.86,76.1 68.86,77.99 69.75,78.88 69.75,80.92 70.21,81.38 70.21,81.63 70.55,81.97 72.37,81.97 72.57,81.76 72.57,81.12 72.07,80.62 71.19,80.62 70.68,80.11 70.68,75.91
SW8 on TOP: 55.88,62.74 56.13,62.48 59.56,62.48 59.82,62.74 59.82,64.01 61.09,65.28 61.09,69.09 61.47,69.47 62.36,69.47 62.74,69.85 62.74,70.1 62.61,70.23 60.2,70.23 59.69,69.72 59.69,66.04 58.01,64.36 56.21,64.36 55.88,64.03
SW8 on SIG_L5: 62.74,62.48 62.74,69.85 62.48,70.1 58.42,70.1 58.17,69.85 58.17,62.48 58.42,62.23 62.48,62.23
SW9 on TOP: 56.95,64.82 58.12,64.82 59.56,66.27 59.56,69.8 60.15,70.38 60.73,70.38 61.04,70.69 61.04,71.58 61.37,71.91 62.69,71.91 62.89,72.11 62.89,72.47 62.43,72.92 58.72,72.92 58.22,72.42 58.22,70.71 57.86,70.36 57.86,67.44 57.4,66.98 56.92,66.98 56.85,66.9 56.85,64.92
U1-8 on TOP: 37.59,67.31 37.59,71.5 37.34,71.75 33.78,71.75 33.3,71.28 33.3,70.33 33.9,69.74 34.77,69.74 35.05,69.46 35.05,67.69 34.92,67.56 34.42,67.56 34.29,67.44 34.29,67.18 34.42,67.06 37.34,67.06
U3-8 on TOP: 30.48,85.66 28.51,85.66 28.07,85.22 28.07,83.44 28.58,82.93 30.86,82.93 31.11,82.68 31.11,80.76 31.49,80.37 35.07,80.37 35.43,80.73 35.43,84.96 35.05,85.34 30.8,85.34
U28_8 on TOP: 108.71,45.09 108.71,49.28 108.46,49.53 105.73,49.53 104.54,48.33 104.54,46.8 104.63,46.71 105.81,46.71 106.13,46.39 106.17,46.39 106.17,45.47 106.05,45.34 105.54,45.34 105.41,45.21 105.41,44.96 105.54,44.83 108.46,44.83
U31_1V8 on SIG_L5: 75.18,73.91 75.18,79.25 75.44,79.5 82.8,79.5 83.06,79.25 83.06,77.72 83.82,76.96 83.82,73.91 83.57,73.66 75.44,73.66
USB1V on TOP: 104.65,26.67 104.65,24.64 106.17,24.64 106.17,26.67 105.92,26.92 104.9,26.92
USB1V on BOTTOM: 103.63,27.56 105.79,27.56 105.92,27.69 106.3,27.69 106.43,27.56 106.43,26.42 106.68,26.16 108.71,26.16 109.22,25.65 109.22,24.64 108.97,24.38 106.68,24.38 104.39,26.67 104.39,27.18 104.27,27.3 103.63,27.3
USB2_DRVBUS on GND_L9: 70.99,47.75 70.74,48.01 70.74,51.56 70.99,51.82 84.96,51.82 85.22,51.56 85.22,49.02 84.96,48.77 83.31,48.77 83.06,49.02 83.06,50.29 82.68,50.67 75.44,50.67 72.52,47.75
USB2V on TOP: 104.65,30.48 104.65,28.45 106.17,28.45 106.17,30.48 105.92,30.73 104.9,30.73
USB2V on BOTTOM: 105.79,30.73 106.55,29.97 108.71,29.97 109.22,29.46 109.22,28.45 108.97,28.19 107.95,28.19 107.7,28.45 107.7,28.7 107.44,28.96 106.68,28.96 106.43,28.7 106.43,28.32 106.3,28.19 105.92,28.19 105.54,27.81 103.63,27.81 103.63,28.07 104.39,28.07 104.78,28.45 104.78,30.48 105.03,30.73
USB3V on TOP: 108.33,30.48 108.33,31.37 106.68,33.02 105.41,33.02 105.16,32.77 105.16,32.13 107.06,30.23 108.08,30.23
USB3V on BOTTOM: 109.22,32.51 109.22,30.73 108.71,30.23 106.81,30.23 105.92,31.11 105.03,31.11 104.39,31.75 104.39,32.26 104.27,32.38 103.63,32.38 103.63,32.64 106.3,32.64 106.43,32.51 106.43,32.26 106.68,32 107.44,32 107.7,32.26 107.7,32.51 107.95,32.77 108.97,32.77
USB4V on TOP: 106.17,34.29 106.17,36.32 104.65,36.32 104.65,34.29 104.9,34.04 105.92,34.04
USB4V on BOTTOM: 106.43,34.29 106.43,33.4 106.3,33.27 105.92,33.27 105.54,32.89 103.63,32.89 103.63,33.15 104.39,33.15 104.78,33.53 104.78,34.42 104.9,34.54 106.17,34.54
USB_5V on TOP: 109.73,50.55 109.47,50.8 109.09,50.8 108.46,50.16 106.67,50.16 106.45,49.94 103.81,49.94 103.22,50.53 103.22,52.06 103.84,52.68 112.47,52.68 112.78,52.37 112.78,45.47 112.52,45.21 109.98,45.21 109.73,45.47
VDAC_3V3 on PWR_L6: 62.87,22.61 62.87,22.86 62.61,23.11 53.85,23.11 53.59,22.86 53.59,12.95 53.85,12.7 62.61,12.7 62.87,12.95
VTT on BOTTOM: outline of 102 points within 31.5,16.51 42.71,51.05
VTT_REFOUT on TOP: 30.1,21.84 30.61,21.84 30.86,22.1 31.24,22.1 31.37,22.23 31.37,23.24 31.24,23.37 30.1,23.37 29.97,23.24 29.97,21.97
VTT_VOSNS on TOP: 25.65,22.1 25.65,23.37 25.78,23.5 27.18,23.5 27.3,23.37 27.3,21.97 27.18,21.84 26.42,21.84 26.29,21.97 25.78,21.97
VUSB_3V3 on INT_L3: 77.98,58.04 78.49,57.53 78.49,52.83 79.76,51.56 79.76,47.12 79.63,46.99 78.36,46.99 77.09,48.26 77.09,67.56 77.34,67.82 77.72,67.82 77.98,67.56
VUSB_3V3 on PWR_L6: 69.6,46.48 69.6,45.47 69.72,45.34 79.5,45.34 79.76,45.59 79.76,47.24 79.5,47.5 79.25,47.5 78.74,46.99 70.1,46.99
VUSB_3V3 on SIG_L10: 70.36,70.36 70.61,70.61 77.72,70.61 77.98,70.36 77.98,67.56 77.72,67.31 70.61,67.31 70.36,67.56
N23730763 on SIG_L5: 65.02,37.85 70.87,37.85 71.12,38.1 71.12,41.53 70.87,41.78 68.07,41.78 67.82,42.04 67.82,51.94 67.56,52.2 62.1,52.2 61.98,52.07 61.98,51.05 64.01,49.02 64.52,49.02 64.77,48.77 64.77,38.1
N24165486 on SIG_L8: 68.96,43.81 69.34,43.81 70.1,44.58 70.1,44.83 69.85,45.09 69.47,45.09 68.83,44.45 68.83,43.94
N24165486 on SIG_L10: 78.11,55.5 78.36,55.24 78.36,49.15 72.64,43.43 68.83,43.43 68.71,43.56 68.71,44.2 69.98,45.47 71.5,45.47 75.69,49.66 75.69,52.7 76.2,53.21 76.2,55.24 76.45,55.5
N26024435 on SIG_L8: 68.45,45.09 68.45,44.7 68.2,44.45 67.56,44.45 67.06,44.96 64.9,44.96 64.64,45.21 64.64,46.48 65.15,46.99 67.06,46.99 67.94,46.1 67.94,45.59
N26024435 on SIG_L10: 67.44,46.99 64.77,46.99 64.64,46.86 64.64,45.47 64.77,45.34 65.28,45.34 66.17,44.45 68.58,44.45 69.85,45.72 71.37,45.72 75.44,49.78 75.44,52.83 75.95,53.34 75.95,55.24 75.69,55.5 75.06,55.5 72.14,52.58 72.14,50.29 68.58,46.74 67.69,46.74

Small or netless copper shapes (teardrops, artwork), in the pictures only: 980 on TOP, 586 on BOTTOM, 280 on INT_L3, 276 on SIG_L5, 4 on PWR_L6, 191 on SIG_L8, 62 on GND_L9, 252 on SIG_L10

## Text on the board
BOTTOM: PCB RevA3 | LAYER 12 | SOLDER
Board Geometry/Soldermask Bottom: SMS
Ref Des/Silkscreen Bottom: A | INSTALLING BATTERY | REMOVE R416 WHEN
TOP: LAYER 1 | COMPONENT
Board Geometry/Soldermask Top: SMC
GND_L2: LAYER 2 | GROUND
INT_L3: LAYER 3 | SIGNAL
GND_L4: LAYER 4 | GROUND
SIG_L5: LAYER 5 | SIGNAL
PWR_L6: LAYER 6 | PWR1
PWR_L7: LAYER 7 | PWR2
SIG_L8: LAYER 8 | SIGNAL
GND_L9: LAYER 9 | GROUND
SIG_L10: LAYER 10 | SIGNAL
GND_L11: LAYER 11 | GROUND
DISPLAY_TOP: SERIAL DEBUG | POWER | SD/eMMC | SATA/SD | FAN | DC | 3.3V | 12V | GND | 5V | AM572X | CURRENT MON | DC IN | RESET | HDMI | uSD | USB3_1 | USB_2/3 | SPC
DIMENSION: 4 PLACES | SCORE LINE | SEE DETAIL "A"
DISPLAY_BOTTOM: JTAG | uSD | SPS
USER_PART_NUM_TOP: TSLKC
USER_PART_NUM_BOTTOM: BSLKC
User.15: TSLK
User.16: BSLK
User.17: ASSEMBLY_TOP
User.18: ASSEMBLY_BOTTOM
User.19: LAYER 1 - PRIMARY SIDE - SIGNAL | LAYER 2 - GROUND PLANE | LAYER 3 - INT. SIGNAL | LAYER 4 - GROUND PLANE | LAYER 5 - INT. SIGNAL | LAYER 6 - POWER PLANE | LAYER 7 - POWER PLANE | LAYER 8 - INT. SIGNAL | LAYER 9 - GROUND PLANE | LAYER 10- INT. SIGNAL | LAYER 11- GROUND PLANE | LAYER 12- SECONDARY SIDE - SIGNAL | COPPER WEIGHT | HALF+PLATING | (OZ) | 50ohm SINGLE ENDED | IMPEDANCE CONTROL | +/- 10% | TRACE WIDTH | TRACE WIDTH / SPACE | 90ohm DIFFERENTIAL | 100ohm DIFFERENTIAL | FINISHED AS SMOOTH WALL BY VENDOR. | PROCESS NOTES: | 2. APPLY LPI SOLDERMASK OVER BARE COPPER (SMOBC), | COLOR: BLACK. SOLDERMASK SHALL CONFIRM TO IPC-SM-840. | CLASS H. CURRENT REV. | 3. SOLDERMASK ARTWORK HAS ZERO (0) OVERSIZED PADS. | FABRICATION VENDOR IS ALLOWED TO ADJUST THE COMPONENT | SOLDERMASK PADS TO MEET THEIR TOOLING REQUIREMENTS. | 4. APPLY LPI SILKSCREEN OR EQUIVALENT PER THE ARTWORK. | COLOR: ORANGE. | 1. PLATE ALL EXPOSED AREAS WITH ELECTROLESS | IMMERSION GOLD, NICKEL 150 MICROINCHES THK MIN | GOLD 5-15 MICROINCHES THK MIN. | SUPPLIED IPC-D-356 NETLIST. | 1. ALL DIMENSIONS ARE IN INCHES, UNLESS | OTHERWISE NOTED. | 2. THE PWB SHALL BE FABRICATED TO IPC-6012, | CLASS 2 AND WORKMANSHIP SHALL CONFORM TO | IPC-A-600, CLASS 2. CURRENT REVISIONS. | 3. BOARD MATERIAL SHALL BE 180 Tg/350 Td ISOLA FR-370HR | OR EQUIVALENT, RoHS COMPLIANT AND LEAD FREE | ASSEMBLY CAPABLE.  BOARD MATERIAL SHALL | MEET OR EXCEED IPC-4101B. COLOR: NATURAL. | 4. BOARD MATERIAL & CONSTRUCTION TO BE U.L. | APPROVED AND MARKED ON THE FINISHED BOARD. | 5. MINIMUM COPPER WALL THICKNESS OF PLATED-THRU | HOLES TO BE .001 INCH, WITH A MINIMUM | ANNULAR RING OF .002 INCH. | 6. OVERALL BOARD THICKNESS TO BE .062 +/- 10% | AND APPLIES AFTER ALL LAMINATION AND PLATING | PROCESSES, MEASURED FROM COPPER TO COPPER. | 7. MAX. WARP & TWIST TO BE .0075 INCHES PER INCH. | 8. BOARD MUST BE ELECTRICALLY TESTED USING | 9. FOR BACKDRILL INFO. SEE GERBER FILE (BACKDRILL_12-4.ART). | FAB NOTES: | ALL DIMENSIONS IN MILS | LAYER# | LAYER STACK-UP | 1 | 4.72 | 3.70 | 5.00/9.00 | 4.50/10.00 | 4.00/10.00 | 3.70/12.00 | SCALE=NONE | o
User.20: D2 | C9 | C8 | 6 | 1 | R290 | C399 | R288 | R286 | G | S | U27 | U1 | C2 | 3 | R291 | Q5 | D1 | D | U3 | C390 | R287 | C400 | R335 | U20 | R289 | C398 | C391 | C392 | R285 | Q6 | L2 | U7 | C12 | TP20 | TP21 | C292 | C306 | C347 | C363 | C283 | 4 | C318 | C335 | C376 | 2 | C284 | R4 | L1 | R2 | C293 | C307 | C319 | C336 | C348 | C364 | C377 | R51 | TP4 | U2 | C295 | 7 | 9 | U13 | C247 | L9 | 28 | L25 | 11 | 12 | 10 | 13 | U18 | L5 | Y2 | L8 | N | C104 | R231 | R244 | M | U21 | D23 | L | K | C252 | 22 | L7 | J | 24 | 23 | H | R395 | L4 | F | L6 | E | Y3 | C271 | C272 | C | D21 | B | L26 | A | L3 | 5 | 25 | Q4 | C50 | C442 | C454 | U31 | J5 | U33 | AH | AF | AD | AB | W | U | R | AG | AE | AC | AA | Y | V | T | P | 15 | C585 | R398 | R399 | U6 | C241 | C242 | C239 | C244 | R202 | R206 | C510 | C522 | U17 | 49 | 64 | U14 | 48 | BAT1 | 14 | C519 | C512 | 18 | 33 | 16 | 17 | 32 | D24 | C550 | C560 | R298 | R293 | C403 | U28 | R292 | L16 | C501 | C561 | C547 | R239 | R195 | R181 | R180 | R193 | R194 | R432 | R190 | R182 | R183 | R187 | R189 | R188 | R192 | R196 | R197 | R191 | D3 | D4 | D5 | D6 | D7 | Y5 | Y6 | D41 | R240 | R309 | R311 | SERIAL DEBUG | R312 | R310 | R313 | C437 | C427 | C426 | C436 | C433 | C5 | C11 | C6 | POWER | R8 | R7 | R35 | R36 | R1 | R34 | FL1 | D12 | D13 | R52 | FL2 | L15 | L13 | D14 | R55 | D15 | C260 | FL3 | R53 | D16 | U12 | U19 | L12 | D17 | FL4 | C100 | D18 | D19 | C261 | R54 | R219 | Q3 | L14 | R232 | R272 | C101 | R271 | R66 | R220 | C103 | C15 | R270 | R215 | D20 | R213 | R269 | R260 | R148 | R216 | U4 | R261 | R262 | R150 | R15 | R64 | C102 | R146 | R217 | R212 | R221 | R147 | D22 | R29 | R144 | R218 | R59 | R62 | R142 | R143 | R267 | R141 | R263 | R222 | R268 | R136 | R264 | R266 | R265 | R89 | R118 | R88 | C457 | R115 | R476 | R87 | C456 | R114 | L21 | R86 | C455 | R113 | R302 | R85 | R112 | R391 | C31 | R84 | R111 | R392 | C447 | C30 | R330 | C32 | C446 | R33 | R329 | R440 | U48 | C511 | C520 | R243 | R204 | C526 | U47 | C518 | C527 | C451 | R441 | C450 | U50 | C562 | C549 | R437 | C409 | U49 | C556 | C551 | R295 | C555 | C410 | C413 | C411 | C406 | C404 | C49 | D27 | D26 | R472 | U51 | R471 | D25 | D33 | R470 | D31 | D38 | R475 | U44 | R474 | R473 | R479 | 36 | 37 | R480 | U15 | S1 | P8 | P10 | P11 | P9 | S2 | P3 | P6 | U5 | U22 | P13 | P15 | SD/eMMC | SATA/SD | FAN | P1 | P2 | DC | U23 | U24 | U26 | U25 | 3.3V | 12V | GND | 5V | AUDIO OUT | AUDIO IN | U11 | AM572X | P5 | J3 | J4 | J6 | J1 | CURRENT MON | DC IN | RESET | HDMI | uSD | USB3_1 | eSATA | USB_2/3 | ASSEMBLY_TOP
User.21: NONE
User.39: FIGURE | SIZE | 6.0 | 8.0 | 12.0 | 20.0 | 26.0 | 31.0 | 35.0 | 36.0 | 38.0 | 40.0 | 52.0 | 62.0 | 75.0 | 91.0 | 102.0 | 125.0 | 45.0 | 63.0 | 67.0 | 128.0 | 41.34x25.59 | 47.24x25.59 | 47.24x39.37 | 59.0x31.0 | 63.0x25.0 | 70.87x39.37 | 79.0x32.0 | 87.0x32.0 | 93.0x50.0 | DRILL CHART: TOP to BOTTOM | ALL UNITS ARE IN MILS | TOLERANCE | +3.0/-3.0 | +0.0/-0.0 | +2.0/-2.0 | +5.0/-5.0 | +4.0/-4.0 | PLATED | NON-PLATED | QTY | 7 | 2601 | 83 | 41 | 2 | 26 | 31 | 8 | 5 | 14 | 4 | 1 | 3 | 12
User.40: NOTES: | - DRILL SIZES LISTED IN LEGEND | ARE CONSIDERED FINISHED. | - VENDOR IS REQUIRED TO SELECT | TOOLING FOR OVERDRILLING. | - LEGEND DOES NOT SPECIFY DEPTH | INTO ADJACENT DIELECTRIC LAYER. | FIGURE | SIZE | 8.0 | BACKDRILL: BOTTOM to GND_L4 | ALL UNITS ARE IN MILS | TOLERANCE | +3.0/-3.0 | PLATED | QTY | 20
